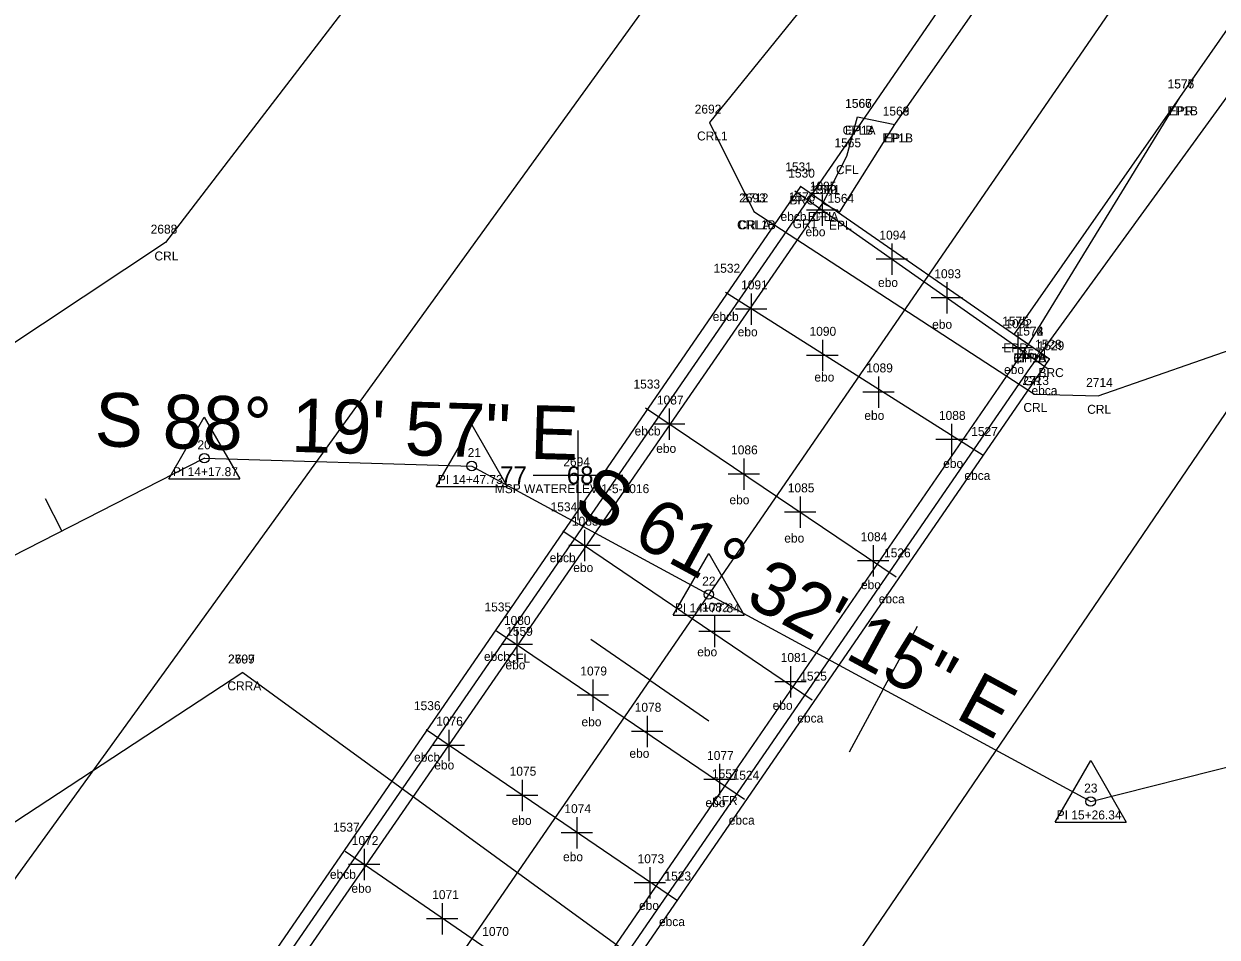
# Model space of a CAD drawing. Extents: x 2266664 to 2272542, y 716533 to 724777.
# Drawn here: x 2267567.2 to 2267700.4, y 717870 to 717971.9 of the extents above; entities that cross this region are included whole.
import ezdxf

# ---------------------------------------------------------------- set-up
doc = ezdxf.new("R2010")
doc.units = 0
for name, color, linetype in [('RD_EX_Bridge', 7, 'Continuous'), ('RD_EX_Bridge_txCode', 7, 'Continuous'), ('RD_EX_Conc', 7, 'Continuous'), ('RD_EX_Conc_txCode', 7, 'Continuous'), ('RD_EX_GuardRail', 7, 'Continuous'), ('RD_EX_GuardRail_txCode', 7, 'Continuous'), ('RD_EX_H2O', 7, 'Continuous'), ('RD_EX_H2O_txCode', 7, 'Continuous'), ('RD_EX_Misc', 7, 'Continuous'), ('RD_EX_Misc_txCode', 7, 'Continuous'), ('RD_EX_Road', 7, 'Continuous'), ('RD_EX_Road_txCode', 7, 'Continuous'), ('RD_EX_VEG', 7, 'Continuous'), ('RD_HC_Cl', 7, 'Continuous'), ('RD_HC_Data', 7, 'Continuous'), ('RD_HC_Data_Tic', 7, 'Continuous'), ('RD_HC_txCode', 7, 'Continuous'), ('RD_SMD_Locator', 7, 'Continuous')]:
    doc.layers.add(name, color=color, linetype=linetype)

msp = doc.modelspace()

# ---------------------------------------------------------------- linework, layer by layer
at = {"layer": 'RD_EX_Bridge'}
msp.add_lwpolyline([(2267579.87, 717786.35), (2267681.7, 717934.49), (2267653.9, 717953.76), (2267551.93, 717805.48), (2267579.87, 717786.35)], dxfattribs=at)
at = {"layer": 'RD_EX_Conc'}
for points in [[(2267554.32, 717803.83), (2267588.43, 717853.38), (2267622.37, 717902.6), (2267656.38, 717951.92), (2267659.04, 717957.15), (2267660.25, 717961.55)], [(2267573.36, 717778.58), (2267574.92, 717783.31), (2267577.48, 717788.12), (2267611.53, 717837.44), (2267645.35, 717886.7), (2267679.35, 717936.13)]]:
    msp.add_lwpolyline(points, dxfattribs=at)
at = {"layer": 'RD_EX_GuardRail'}
for points in [[(2267481.72, 717701.57), (2267534.2, 717777.68), (2267554.26, 717806.46), (2267653.96, 717951.11), (2267712.38, 718036.08), (2267729.57, 718061.3)], [(2267506.03, 717677.39), (2267559.71, 717759.86), (2267580, 717788.93), (2267679.56, 717933.57), (2267740.09, 718016.9), (2267757.63, 718042.07)]]:
    msp.add_lwpolyline(points, dxfattribs=at)
at = {"layer": 'RD_EX_H2O'}
for points in [[(2267686.36, 718130.99), (2267690.83, 718106.74), (2267686.34, 718089.44), (2267642.41, 718025), (2267582.98, 717947.51), (2267550.82, 717926.2), (2267512.27, 717909.43), (2267438.37, 717872.3), (2267354.06, 717821.29), (2267269.27, 717778.74), (2267209.58, 717745.96)], [(2267669.59, 718017.38), (2267662.05, 717993.87), (2267655.29, 717975.24), (2267643.73, 717960.91), (2267648.67, 717950.99)], [(2267648.67, 717950.99), (2267680, 717930.6), (2267687.12, 717930.39), (2267710.19, 717938.44), (2267744.82, 717946.17), (2267816.91, 717950.39), (2267875.61, 717952.39), (2267928.18, 717957.12), (2267936.35, 717960.67), (2267968.01, 717966.35), (2267984.51, 717962.62), (2267996.02, 717960.08)], [(2267591.63, 717899.51), (2267531.13, 717859.82), (2267501.13, 717852.09), (2267465.59, 717837.13), (2267453.8, 717838.63), (2267369.2, 717795.39), (2267285.05, 717748.63), (2267226.79, 717709.87)], [(2267591.63, 717899.51), (2267637.77, 717865.9), (2267685.44, 717839.85), (2267756.83, 717863.74), (2267826.13, 717888.16), (2267866.36, 717887.16), (2267930.84, 717899.12), (2268026.36, 717789.97), (2268079.49, 717725.08)]]:
    msp.add_lwpolyline(points, dxfattribs=at)
at = {"layer": 'RD_EX_Misc'}
for p, q in [((2267681.41, 717933.45), (2267653.24, 717953.26)), ((2267656.3, 717952.86), (2267656.3, 717949.36)), ((2267658.05, 717951.11), (2267654.55, 717951.11)), ((2267664.07, 717947.39), (2267664.07, 717943.89)), ((2267665.82, 717945.64), (2267662.32, 717945.64)), ((2267670.21, 717943.08), (2267670.21, 717939.58)), ((2267674.29, 717923.72), (2267645.51, 717941.94)), ((2267648.36, 717941.83), (2267648.36, 717938.33)), ((2267671.96, 717941.33), (2267668.46, 717941.33)), ((2267650.11, 717940.08), (2267646.61, 717940.08)), ((2267678.14, 717937.5), (2267678.14, 717934)), ((2267656.32, 717936.65), (2267656.32, 717933.15)), ((2267658.07, 717934.9), (2267654.57, 717934.9)), ((2267679.89, 717935.75), (2267676.39, 717935.75)), ((2267662.6, 717932.56), (2267662.6, 717929.06)), ((2267664.35, 717930.81), (2267660.85, 717930.81)), ((2267664.58, 717910.16), (2267636.57, 717929.01)), ((2267639.23, 717928.98), (2267639.23, 717925.48)), ((2267629.05, 717916.53), (2267629.05, 717926.53)), ((2267640.98, 717927.23), (2267637.48, 717927.23)), ((2267670.73, 717927.26), (2267670.73, 717923.76)), ((2267672.48, 717925.51), (2267668.98, 717925.51)), ((2267647.54, 717923.41), (2267647.54, 717919.91)), ((2267624.05, 717921.53), (2267634.05, 717921.53)), ((2267649.29, 717921.66), (2267645.79, 717921.66)), ((2267653.85, 717919.17), (2267653.85, 717915.67)), ((2267655.6, 717917.42), (2267652.1, 717917.42)), ((2267655.19, 717896.4), (2267627.33, 717915.3)), ((2267629.75, 717915.45), (2267629.75, 717911.95)), ((2267631.5, 717913.7), (2267628, 717913.7)), ((2267661.98, 717913.71), (2267661.98, 717910.21)), ((2267663.73, 717911.96), (2267660.23, 717911.96)), ((2267644.27, 717905.85), (2267644.27, 717902.35)), ((2267647.64, 717885.33), (2267619.95, 717904.12)), ((2267622.2, 717904.37), (2267622.2, 717900.87)), ((2267646.02, 717904.1), (2267642.52, 717904.1)), ((2267623.95, 717902.62), (2267620.45, 717902.62)), ((2267652.78, 717900.23), (2267652.78, 717896.73)), ((2267630.69, 717898.72), (2267630.69, 717895.22)), ((2267654.53, 717898.48), (2267651.03, 717898.48)), ((2267632.44, 717896.97), (2267628.94, 717896.97)), ((2267636.76, 717894.67), (2267636.76, 717891.17)), ((2267640.04, 717874.08), (2267612.09, 717893.1)), ((2267614.62, 717893.12), (2267614.62, 717889.62)), ((2267638.51, 717892.92), (2267635.01, 717892.92)), ((2267616.37, 717891.37), (2267612.87, 717891.37)), ((2267644.83, 717889.29), (2267644.83, 717885.79)), ((2267622.79, 717887.53), (2267622.79, 717884.03)), ((2267646.58, 717887.54), (2267643.08, 717887.54)), ((2267624.54, 717885.78), (2267621.04, 717885.78)), ((2267628.9, 717883.35), (2267628.9, 717879.85)), ((2267630.65, 717881.6), (2267627.15, 717881.6)), ((2267630.59, 717860.59), (2267603.04, 717879.53)), ((2267605.16, 717879.8), (2267605.16, 717876.3)), ((2267606.91, 717878.05), (2267603.41, 717878.05)), ((2267637.07, 717877.76), (2267637.07, 717874.26)), ((2267638.82, 717876.01), (2267635.32, 717876.01)), ((2267613.86, 717873.75), (2267613.86, 717870.25)), ((2267615.61, 717872), (2267612.11, 717872))]:
    msp.add_line(p, q, dxfattribs=at)
at = {"layer": 'RD_EX_Road'}
for p, q in [((2267679.35, 717936.13), (2267696.23, 717963.72)), ((2267660.25, 717961.55), (2267664.43, 717960.69))]:
    msp.add_line(p, q, dxfattribs=at)
for points in [[(2267656.38, 717951.92), (2267658.27, 717950.95), (2267664.43, 717960.69), (2267715.64, 718033.91), (2267761.28, 718100.58), (2267786.41, 718137.16), (2267833.26, 718204.57)], [(2267679.35, 717936.13), (2267677.75, 717937.24), (2267696.23, 717963.72), (2267735.24, 718019.64), (2267790.98, 718100.9), (2267816.93, 718136.13), (2267852.97, 718190.65)]]:
    msp.add_lwpolyline(points, dxfattribs=at)
at = {"layer": 'RD_EX_VEG'}
for points in [[(2267134.22, 717341.52), (2267165.25, 717311.03), (2267183.13, 717334.8), (2267190.72, 717329.71), (2267298.34, 717493.63), (2267449.37, 717714.99), (2267742.75, 718120.7)], [(2267330.42, 717346.12), (2267314.92, 717369.68), (2267464.99, 717583.46), (2267551.97, 717708.99), (2267721.53, 717958.13), (2267810.77, 718081.35), (2267867.02, 718039.18)]]:
    msp.add_lwpolyline(points, dxfattribs=at)
at = {"layer": 'RD_HC_Cl'}
for p, q in [((2267342.91, 717471.2), (2272360.46, 724762.59)), ((2267361.63, 717808.34), (2267587.32, 717923.43)), ((2267587.32, 717923.43), (2267617.17, 717922.56)), ((2267617.17, 717922.56), (2267686.28, 717885.1)), ((2267686.28, 717885.1), (2267821.52, 717919.27))]:
    msp.add_line(p, q, dxfattribs=at)
at = {"layer": 'RD_HC_Data'}
for p, q in [((2267583.35, 717921.14), (2267587.32, 717928.02)), ((2267587.32, 717928.02), (2267591.29, 717921.14)), ((2267613.2, 717920.27), (2267617.17, 717927.15)), ((2267617.17, 717927.15), (2267621.14, 717920.27)), ((2267583.35, 717921.14), (2267591.29, 717921.14)), ((2267613.2, 717920.27), (2267621.14, 717920.27)), ((2267639.67, 717905.92), (2267643.64, 717912.8)), ((2267643.64, 717912.8), (2267647.61, 717905.92)), ((2267639.67, 717905.92), (2267647.61, 717905.92)), ((2267682.31, 717882.8), (2267686.28, 717889.68)), ((2267686.28, 717889.68), (2267690.25, 717882.8)), ((2267682.31, 717882.8), (2267690.25, 717882.8))]:
    msp.add_line(p, q, dxfattribs=at)
for centre in [(2267587.32, 717923.43), (2267617.17, 717922.56), (2267643.64, 717908.21), (2267686.28, 717885.1)]:
    msp.add_circle(centre, 0.529, dxfattribs=at)
at = {"layer": 'RD_HC_Data_Tic'}
for p, q in [((2267571.4, 717915.31), (2267569.59, 717918.88)), ((2267663.12, 717897.65), (2267666.93, 717904.68)), ((2267637.06, 717898.66), (2267630.47, 717903.19)), ((2267637.06, 717898.66), (2267643.65, 717894.12)), ((2267663.12, 717897.65), (2267659.31, 717890.62))]:
    msp.add_line(p, q, dxfattribs=at)
at = {"layer": 'RD_SMD_Locator'}
for centre in [(2267696.23, 717963.72), (2267696.23, 717963.72), (2267660.25, 717961.55), (2267660.25, 717961.55), (2267643.73, 717960.91), (2267664.43, 717960.69), (2267664.43, 717960.69), (2267659.04, 717957.15), (2267653.9, 717953.76), (2267656.38, 717951.92), (2267656.38, 717951.92), (2267648.67, 717950.99), (2267648.67, 717950.99), (2267653.96, 717951.11), (2267658.27, 717950.95), (2267582.98, 717947.51), (2267677.75, 717937.24), (2267679.35, 717936.13), (2267679.35, 717936.13), (2267679.35, 717936.13), (2267681.7, 717934.49), (2267679.56, 717933.57), (2267680, 717930.6), (2267687.12, 717930.39), (2267587.32, 717923.43), (2267617.17, 717922.56), (2267643.64, 717908.21), (2267622.37, 717902.6), (2267591.63, 717899.51), (2267591.63, 717899.51), (2267645.35, 717886.7), (2267686.28, 717885.1)]:
    msp.add_circle(centre, 0.001, dxfattribs=at)

# ---------------------------------------------------------------- texts
at = {"layer": 'RD_EX_Bridge_txCode'}
for s, p in [('1530', (2267652.51, 717954.76)), ('BRC', (2267652.65, 717951.76)), ('1529', (2267680.35, 717935.49)), ('BRC', (2267680.45, 717932.49))]:
    msp.add_text(s, height=1, dxfattribs=at).set_placement(p)
at = {"layer": 'RD_EX_Conc_txCode'}
for s, p in [('1566', (2267658.86, 717962.55)), ('CFLB', (2267658.58, 717959.55)), ('1565', (2267657.67, 717958.15)), ('CFL', (2267657.84, 717955.15)), ('1560', (2267654.97, 717952.92)), ('CFL', (2267655.18, 717949.92)), ('1572', (2267678.01, 717937.13)), ('CFRB', (2267677.65, 717934.13)), ('1559', (2267621.02, 717903.6)), ('CFL', (2267621.17, 717900.6)), ('1557', (2267644, 717887.7)), ('CFR', (2267644.12, 717884.7))]:
    msp.add_text(s, height=1, dxfattribs=at).set_placement(p)
at = {"layer": 'RD_EX_GuardRail_txCode'}
for s, p in [('1570', (2267652.57, 717952.11)), ('GR1', (2267653.01, 717949.11)), ('1571', (2267678.5, 717934.57)), ('GR', (2267678.78, 717931.57))]:
    msp.add_text(s, height=1, dxfattribs=at).set_placement(p)
at = {"layer": 'RD_EX_H2O_txCode'}
for s, p in [('2692', (2267642.07, 717961.91)), ('CRL1', (2267642.33, 717958.91)), ('2693', (2267647.02, 717951.99)), ('2712', (2267647.32, 717951.99)), ('2688', (2267581.33, 717948.51)), ('CRL1B', (2267646.8, 717948.99)), ('CRLA', (2267646.95, 717948.99)), ('CRL', (2267581.75, 717945.51)), ('2713', (2267678.65, 717931.6)), ('2714', (2267685.77, 717931.39)), ('CRL', (2267678.77, 717928.6)), ('CRL', (2267685.89, 717928.39)), ('2709', (2267589.96, 717900.51)), ('2697', (2267589.98, 717900.51)), ('CRRA', (2267589.89, 717897.51)), ('CRRA', (2267589.89, 717897.51))]:
    msp.add_text(s, height=1, dxfattribs=at).set_placement(p)
at = {"layer": 'RD_EX_Misc_txCode'}
for s, height, p in [('1531', 1, (2267652.18, 717955.46)), ('1095', 1, (2267654.92, 717953.31)), ('ebcb', 1, (2267651.65, 717949.92)), ('ebo', 1, (2267654.44, 717948.21)), ('1094', 1, (2267662.69, 717947.84)), ('1532', 1, (2267644.17, 717944.14)), ('1093', 1, (2267668.82, 717943.53)), ('1091', 1, (2267647.25, 717942.28)), ('ebo', 1, (2267662.54, 717942.55)), ('ebcb', 1, (2267644.08, 717938.75)), ('ebo', 1, (2267668.58, 717937.88)), ('1092', 1, (2267676.75, 717937.95)), ('ebo', 1, (2267646.87, 717937.04)), ('1090', 1, (2267654.89, 717937.1)), ('1528', 1, (2267680.07, 717935.65)), ('1089', 1, (2267661.22, 717933.01)), ('ebo', 1, (2267676.61, 717932.83)), ('1533', 1, (2267635.23, 717931.21)), ('ebo', 1, (2267655.43, 717931.99)), ('1087', 1, (2267637.85, 717929.43)), ('ebca', 1, (2267679.67, 717930.49)), ('ebo', 1, (2267661.01, 717927.71)), ('1088', 1, (2267669.34, 717927.71)), ('ebcb', 1, (2267635.36, 717925.97)), ('1527', 1, (2267672.94, 717925.92)), ('ebo', 1, (2267637.77, 717924.03)), ('1086', 1, (2267646.13, 717923.86)), ('77      68', 2, (2267620.36, 717920.53)), ('2694', 1, (2267627.4, 717922.53)), ('ebo', 1, (2267669.81, 717922.35)), ('ebca', 1, (2267672.18, 717921)), ('MSP WATERELEV.1-5-2016', 1, (2267619.75, 717919.53)), ('1085', 1, (2267652.46, 717919.62)), ('1534', 1, (2267625.98, 717917.5)), ('ebo', 1, (2267645.95, 717918.29)), ('1083', 1, (2267628.36, 717915.9)), ('ebo', 1, (2267652.07, 717914.01)), ('1084', 1, (2267660.6, 717914.16)), ('1526', 1, (2267663.21, 717912.36)), ('ebcb', 1, (2267625.88, 717911.82)), ('ebo', 1, (2267628.51, 717910.72)), ('ebo', 1, (2267660.63, 717908.81)), ('ebca', 1, (2267662.62, 717907.23)), ('1535', 1, (2267618.6, 717906.32)), ('1082', 1, (2267642.88, 717906.3)), ('1080', 1, (2267620.77, 717904.82)), ('ebcb', 1, (2267618.54, 717900.8)), ('ebo', 1, (2267642.35, 717901.31)), ('1081', 1, (2267651.67, 717900.68)), ('ebo', 1, (2267620.94, 717899.85)), ('1079', 1, (2267629.3, 717899.17)), ('1525', 1, (2267653.85, 717898.6)), ('1536', 1, (2267610.72, 717895.3)), ('1078', 1, (2267635.37, 717895.12)), ('ebo', 1, (2267650.77, 717895.34)), ('1076', 1, (2267613.21, 717893.57)), ('ebo', 1, (2267629.43, 717893.5)), ('ebca', 1, (2267653.52, 717893.92)), ('ebcb', 1, (2267610.74, 717889.55)), ('ebo', 1, (2267634.78, 717889.98)), ('1077', 1, (2267643.45, 717889.74)), ('ebo', 1, (2267612.99, 717888.68)), ('1075', 1, (2267621.41, 717887.98)), ('1524', 1, (2267646.3, 717887.53)), ('ebo', 1, (2267643.27, 717884.47)), ('1074', 1, (2267627.52, 717883.8)), ('1537', 1, (2267601.69, 717881.73)), ('ebo', 1, (2267621.63, 717882.49)), ('ebca', 1, (2267645.87, 717882.52)), ('1072', 1, (2267603.78, 717880.25)), ('ebo', 1, (2267627.37, 717878.43)), ('1073', 1, (2267635.69, 717878.21)), ('ebcb', 1, (2267601.34, 717876.47)), ('1523', 1, (2267638.69, 717876.28)), ('ebo', 1, (2267603.74, 717874.91)), ('1071', 1, (2267612.76, 717874.2)), ('ebo', 1, (2267635.85, 717873)), ('ebca', 1, (2267638.08, 717871.19)), ('1070', 1, (2267618.35, 717870.09))]:
    msp.add_text(s, height=height, dxfattribs=at).set_placement(p)
at = {"layer": 'RD_EX_Road_txCode'}
for s, p in [('1576', (2267694.86, 717964.72)), ('1577', (2267694.88, 717964.72)), ('1567', (2267658.88, 717962.55)), ('1568', (2267663.06, 717961.69)), ('1569', (2267663.06, 717961.69)), ('EP1B', (2267694.83, 717961.72)), ('EPR', (2267695, 717961.72)), ('EP1A', (2267658.84, 717959.55)), ('EP1B', (2267663.03, 717958.69)), ('EPL', (2267663.22, 717958.69)), ('1561', (2267655.3, 717952.92)), ('1564', (2267656.9, 717951.95)), ('EPLA', (2267654.69, 717949.92)), ('EPL', (2267657.06, 717948.95)), ('1575', (2267676.4, 717938.24)), ('1573', (2267678.01, 717937.13)), ('1574', (2267678.01, 717937.13)), ('EPR', (2267676.52, 717935.24)), ('EPRA', (2267677.64, 717934.13)), ('EP1A', (2267677.94, 717934.13))]:
    msp.add_text(s, height=1, dxfattribs=at).set_placement(p)
at = {"layer": 'RD_HC_Data'}
for s, rotation, p in [('S 88%%d 19\' 57" E', 358.3326, (2267575.04, 717924.79)), ('S 61%%d 32\' 15" E', 331.5376, (2267628.25, 717917.69))]:
    msp.add_text(s, height=6, rotation=rotation, dxfattribs=at).set_placement(p)
at = {"layer": 'RD_HC_txCode'}
for s, p in [('20', (2267586.55, 717924.43)), ('21', (2267616.72, 717923.56)), ('PI 14+17.87', (2267583.82, 717921.43)), ('PI 14+47.73', (2267613.39, 717920.56)), ('22', (2267642.91, 717909.21)), ('PI 14+77.84', (2267639.86, 717906.21)), ('23', (2267685.55, 717886.1)), ('PI 15+26.34', (2267682.48, 717883.1))]:
    msp.add_text(s, height=1, dxfattribs=at).set_placement(p)

doc.saveas('drawing.dxf')
